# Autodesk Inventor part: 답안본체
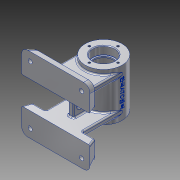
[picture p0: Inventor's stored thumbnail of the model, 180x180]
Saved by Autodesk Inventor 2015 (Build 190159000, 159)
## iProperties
Created: 2016-07
Part Number: 답안본체
Material: 알루미늄 6061
Document SubType Name: Modeling
Designer: owner
Density: 2.7 g/cm^3
Appearance: 알루미늄 - 평지
Author: owner
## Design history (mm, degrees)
sketch "스케치1"
  geometry: C1 r 27 at (0, 0); 1 further point
  constraints: 1 centre point, 1 coincident
  dimensions: "d0" = 54 diameter of C1
extrude "돌출1" new body sketch "스케치1" distance "d1" = 70; taper "d2" = 0 deg
node "작업 평면1"
sketch "스케치3"
  geometry: L1 (50, -20)-(-50, -20); L2 (-50, -20)-(-50, 15); L3 (-50, 15)-(50, 15); L4 (50, 15)-(50, -20); L5 (50, 55)-(-50, 55); L6 (-50, 55)-(-50, 90); L7 (-50, 90)-(50, 90); L8 (50, 90)-(50, 55); L9 (-27, 0)-(27, 0) reference; L10 (-27, 0)-(-27, 70) reference; 6 further points
  constraints: 16 end point, 4 midpoint, 4 parallel, 2 horizontal, 2 perpendicular, 2 vertical alignment, 1 coincident
  dimensions: "d10" = 100 distance of L1.start L1.end; "d11" = 100 distance of L6.end L7.end; "d12" = 35 distance of L3.end L1.start; "d13" = 35 distance of L7.end L5.start; "d14" = 55 distance from line of L7 point (-27, 35); "d15" = 110 distance between parallel lines of L7 L1
extrude "돌출2" join sketch "스케치3" distance "d16" = 12; taper "d17" = 0 deg
node "작업 평면2"
sketch "스케치4"
  geometry: L1 (27, 70)-(-27, 70) reference; C1 r 5 at (0, 48); 2 further points
  constraints: 1 centre point, 1 midpoint, 1 vertical alignment
  dimensions: "d19" = 10 diameter of C1; "d20" = 22 distance from line of L1 C1.centre
extrude "돌출3" join sketch "스케치4" stored distance "d21" = 12; taper "d22" = 0 deg
node "작업 평면3"
node "작업 평면4"
sketch "스케치6"
  geometry: L1 (-50, -70)-(-50, -58) reference; L2 (-50, -58)-(50, -58) reference; L3 (50, -58)-(50, -70) reference; L4 (50, -70)-(-50, -70) reference; L5 (-27, 0)-(-27, -60.669); L6 (27, 0)-(27, -60.669); L7 (-27, -60.669)-(27, -60.669); L8 (-27, 0)-(27, 0); A1 r 27 centre (0, 0) between (-27, 0) and (27, 0) reference; 1 further point
  constraints: 8 end point, 2 horizontal, 2 point on circle, 2 tangent, 1 perpendicular, 1 vertical
  dimensions: "d34" = 60.66852 distance of L6.start L6.end
extrude "돌출4" join sketch "스케치6" distance "d35" = 8; taper "d36" = 0 deg
sketch "스케치7"
  geometry: L1 (-70, 90)-(-58, 90) reference; L2 (-58, 90)-(-58, 63) reference; L3 (-58, 63)-(-27, 63) reference; L4 (-27, 63)-(-27, 70) reference; L5 (-27, 70)-(27, 70) reference; L6 (27, 70)-(27, 53) reference; L7 (30, 43)-(27, 43) reference; L8 (30, 53)-(30, 43) reference; L9 (27, 53)-(30, 53) reference; L10 (27, 43)-(27, 0) reference; L11 (27, 0)-(-27, 0) reference; L12 (-27, 0)-(-27, 7) reference; L13 (-27, 7)-(-58, 7) reference; L14 (-58, 7)-(-58, -20) reference; L15 (-58, -20)-(-70, -20) reference; L16 (-70, -20)-(-70, 15) reference; L17 (-70, 15)-(-27, 15) reference; L18 (-27, 15)-(-27, 55) reference; L19 (-27, 55)-(-70, 55) reference; L20 (-70, 55)-(-70, 90) reference; L21 (-48, 55)-(-48, 15); L22 (-48, 55)-(-18.614, 55); L23 (-48, 15)-(-18.614, 15); L24 (-18.614, 55)-(-18.614, 15); L25 (-38, 43)-(-38, 27); L26 (-41.5, 43)-(-41.5, 27); L27 (-34.5, 27)-(-34.5, 43); L28 (-38, 46.5)-(-38, 23.5); A1 r 3.5 centre (-38, 43) between (-34.5, 43) and (-41.5, 43); A2 r 3.5 centre (-38, 27) between (-41.5, 27) and (-34.5, 27); 3 further points
  constraints: 18 end point, 6 point on circle, 4 tangent, 2 centre point, 2 horizontal, 2 midpoint, 2 point on line, 2 vertical, 1 horizontal alignment, 1 parallel, 1 perpendicular
  dimensions: "d37" = 21 distance between parallel lines of L21 L4; "d38" = 29.38647 distance of L21.start L22.end; "d39" = 3.5 radius of A2; "d40" = 32 distance from line of L16 point (-38, 35); "d42" = 11.5 distance of point (-38, 35) L28.start
extrude "돌출5" join sketch "스케치7" stored distance "d43" = 8; taper "d44" = 0 deg
sketch "스케치8"
  geometry: L1 (-50, -55)-(-50, -90) reference; L2 (-50, -90)-(50, -90) reference; L3 (-27, -15)-(-27, -7) reference; L4 (-27, -7)-(27, -7) reference; L5 (27, -7)-(27, -15) reference; L6 (27, -15)-(50, -15) reference; L7 (50, -15)-(50, 20) reference; L8 (50, 20)-(-50, 20) reference; L9 (-50, 20)-(-50, -15) reference; L10 (-50, -15)-(-27, -15) reference; 5 further points
  dimensions: "d45" = 12.5 distance from line of L2 point (-37.5, -77.5); "d46" = 12.5 distance from line of L2 point (37.5, -77.5); "d48" = 85 distance of point (-37.5, -77.5) point (-37.5, 7.5); "d49" = 12.5 distance from line of L9 point (-37.5, 7.5); "d50" = 12.5 distance from line of L1 point (-37.5, -77.5); "d51" = 12.5 distance from line of L7 point (37.5, 7.5); "d52" = 12.5 distance from line of point (37.5, 7.5) L8; "d54" = 75 distance of point (37.5, -77.5) point (-37.5, -77.5)
hole "구멍1" sketch "스케치8" at (-37.5, 7.5), (37.5, 7.5), (-37.5, -77.5), (37.5, -77.5) diameter "d55" = 6; stored, may be unused: countersink angle "d59" = 90 deg, drill point angle "d61" = 0 deg; dims "d56" = 6, "d57" = 10, "d58" = 4, "d60" = 20
node "작업 평면5"
sketch "스케치9"
  geometry: L1 (27, 70)-(-27, 70) reference; 2 further points
  constraints: 1 vertical alignment, 1 other
  dimensions: "d63" = 35 distance from line of L1 point (0, 35)
feature "엠보싱1" sketch "스케치9" dims "d64" = 0.5, "d65" = 0
node "작업 평면6"
sketch "스케치10"
  geometry: L1 (-70, 55)-(-70, 90) reference; L2 (-70, 55)-(-58, 55) reference; L3 (-58, 90)-(-58, 55) reference; L4 (-70, 90)-(-58, 90) reference; L5 (-70, -10.5)-(-62, -10.5) reference; L6 (-70, -20)-(-70, 15) reference; L7 (-70, -20)-(-58, -20) reference; L8 (-58, 15)-(-58, -20) reference; L9 (-70, 15)-(-58, 15) reference; L10 (-70, 90)-(-58, 85.632); L11 (-70, -20)-(-58, -15.632); L12 (-70, 90)-(-58, 90); L13 (-70, -20)-(-58, -20); L14 (-58, 90)-(-58, 85.632); L15 (-58, -20)-(-58, -15.632); L16 (-58, 90)-(-58, 85.632); L17 (-58, 90)-(-70, 90); 1 further point
  constraints: 16 end point, 2 collinear, 1 horizontal
  dimensions: "d67" = 110 deg angle of L1 L10; "d68" = 110 deg angle of L6 L11; "d69" = 4.36764 distance of L10.end L3.start; "d70" = 4.36764 distance of L7.end L11.end
extrude "돌출6" cut sketch "스케치10" stored distance "d71" = 8; taper "d72" = 0 deg
node "작업 평면7"
sketch "스케치11"
  geometry: L1 (-50, -70)-(-50, -58) reference; L2 (50, -70)-(-50, -70) reference; L3 (50, -58)-(50, -70) reference; L4 (-50, -58)-(50, -58) reference; L5 (-50, -70)-(-50, -58); L6 (50, -70)-(50, -58); L7 (-50, -70)-(-45.632, -58); L8 (50, -70)-(45.632, -58); L9 (-50, -58)-(-45.632, -58); L10 (50, -58)-(45.632, -58); 1 further point
  constraints: 12 end point, 2 vertical
  dimensions: "d74" = 110 deg angle of L2 L7; "d75" = 110 deg angle of L2 L8; "d76" = 4.36764 distance of L7.end L1.end; "d77" = 4.36764 distance of L3.start L8.end
extrude "돌출7" cut sketch "스케치11" stored distance "d78" = 8; taper "d79" = 0 deg
hole "구멍2" diameter "d82" = 32; stored, may be unused: countersink angle "d86" = 90 deg, drill point angle "d88" = 0 deg; dims "d80" = 10, "d81" = 10, "d83" = 6, "d84" = 10, "d85" = 4, "d87" = 12
hole "구멍3" diameter "d91" = 28; stored, may be unused: countersink angle "d95" = 90 deg, drill point angle "d97" = 0 deg; dims "d89" = 10, "d90" = 10, "d92" = 6, "d93" = 10, "d94" = 4, "d96" = 2
hole "구멍4" diameter "d100" = 44; stored, may be unused: countersink angle "d104" = 90 deg, drill point angle "d106" = 0 deg; dims "d98" = 10, "d99" = 10, "d101" = 6, "d102" = 10, "d103" = 4, "d105" = 42
chamfer "모따기1" distance "d107" = 1; stored, may be unused: second distance "d108" = 2, angle "d109" = 45 deg
fillet "모깎기1" dims "d110" = 0.3
fillet "모깎기2" dims "d111" = 3
hole "구멍5" diameter "d114" = 5.188; stored, may be unused: countersink angle "d118" = 90 deg, drill point angle "d120" = 118 deg; dims "d112" = 10, "d113" = 10, "d115" = 12, "d116" = 10, "d117" = 4, "d119" = 16
sketch "스케치12" dims "d130" = 42
  geometry: C1 r 27 at (0, 0) reference; C2 r 17 at (0, 0) reference; 2 further points
  constraints: 2 vertical alignment, 1 coincident, 2 other
hole "구멍7" sketch "스케치12" at (0, 21) diameter "d131" = 3.242; stored, may be unused: countersink angle "d135" = 82 deg, drill point angle "d137" = 118 deg; dims "d132" = 8, "d133" = 3.023, "d134" = 4, "d136" = 10
fillet "모깎기3" dims "d141" = 10, "d142" = 2
fillet "모깎기4" dims "d143" = 2
fillet "모깎기5" dims "d144" = 2
fillet "모깎기6" dims "d145" = 2
fillet "모깎기7" dims "d146" = 2
fillet "모깎기8" dims "d147" = 2
fillet "모깎기9" dims "d148" = 2
fillet "모깎기10" dims "d149" = 2
fillet "모깎기11" dims "d150" = 2
chamfer "모따기2" distance "d151" = 1; stored, may be unused: second distance "d152" = 2, angle "d153" = 45 deg
sketch "스케치13"
  geometry: L1 (0, 0)-(0, -27); L2 (0, 0)-(-15.898, -25.441); L3 (-15.898, -25.441)-(-20.986, -22.262); L4 (-15.898, -25.441)-(-10.809, -28.621); L5 (-20.986, -22.262)-(-17.698, -17); L6 (-10.809, -28.621)-(-7.521, -23.359); L7 (-7.521, -23.359)-(-17.698, -17); L8 (-15.898, -25.441)-(-12.61, -20.18); C1 r 1.621 at (0, 21) reference; C2 r 1.621 at (-21, 0) reference; C3 r 1.621 at (0, -21) reference; C4 r 1.621 at (21, 0) reference; C5 r 17 at (0, 0) reference; 2 further points
  constraints: 16 end point, 5 perpendicular, 1 midpoint, 1 vertical, 1 vertical alignment, 1 other
  dimensions: "d154" = 32 deg angle of L1 L2; "d155" = 30 distance of L1.start L2.end; "d157" = 6 distance of L2.end L4.end; "d158" = 12 distance of L3.end L4.end; "d159" = 6.20475 distance of L3.end L5.end
revolve "회전2" sketch "스케치13" stored, may be unused: angle "d160" = 90 deg
fillet "모깎기12" dims "d161" = 2
hole "구멍8" diameter "d164" = 5.188; stored, may be unused: countersink angle "d168" = 90 deg, drill point angle "d170" = 118 deg; dims "d162" = 10, "d163" = 10, "d165" = 45, "d166" = 4, "d167" = 2, "d169" = 50
node "솔리드1"
mirror "대칭1"
mirror "대칭2"
mirror "대칭3"
pattern_circular "원형 패턴1" dims angle "d139" = 360 deg
mirror "대칭4"
node "투영된 루프2"
node "투영된 루프3"
node "투영된 루프4"
node "투영된 루프5"
node "투영된 루프6"
node "절단 모서리 투영2"
node "절단 모서리 투영3"
other parameters: "d23" = 35, "d62" = 27, "d73" = 55
